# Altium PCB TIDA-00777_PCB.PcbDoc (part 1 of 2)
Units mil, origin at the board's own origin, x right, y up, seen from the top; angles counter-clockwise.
Board outline 1968.5 x 2165.35 mil, 4 copper layers (Top Layer, GND, +2.5V, Bottom Layer), stack 30.48 mil thick; 147 components, 52 nets, 290 pads, 85 vias.
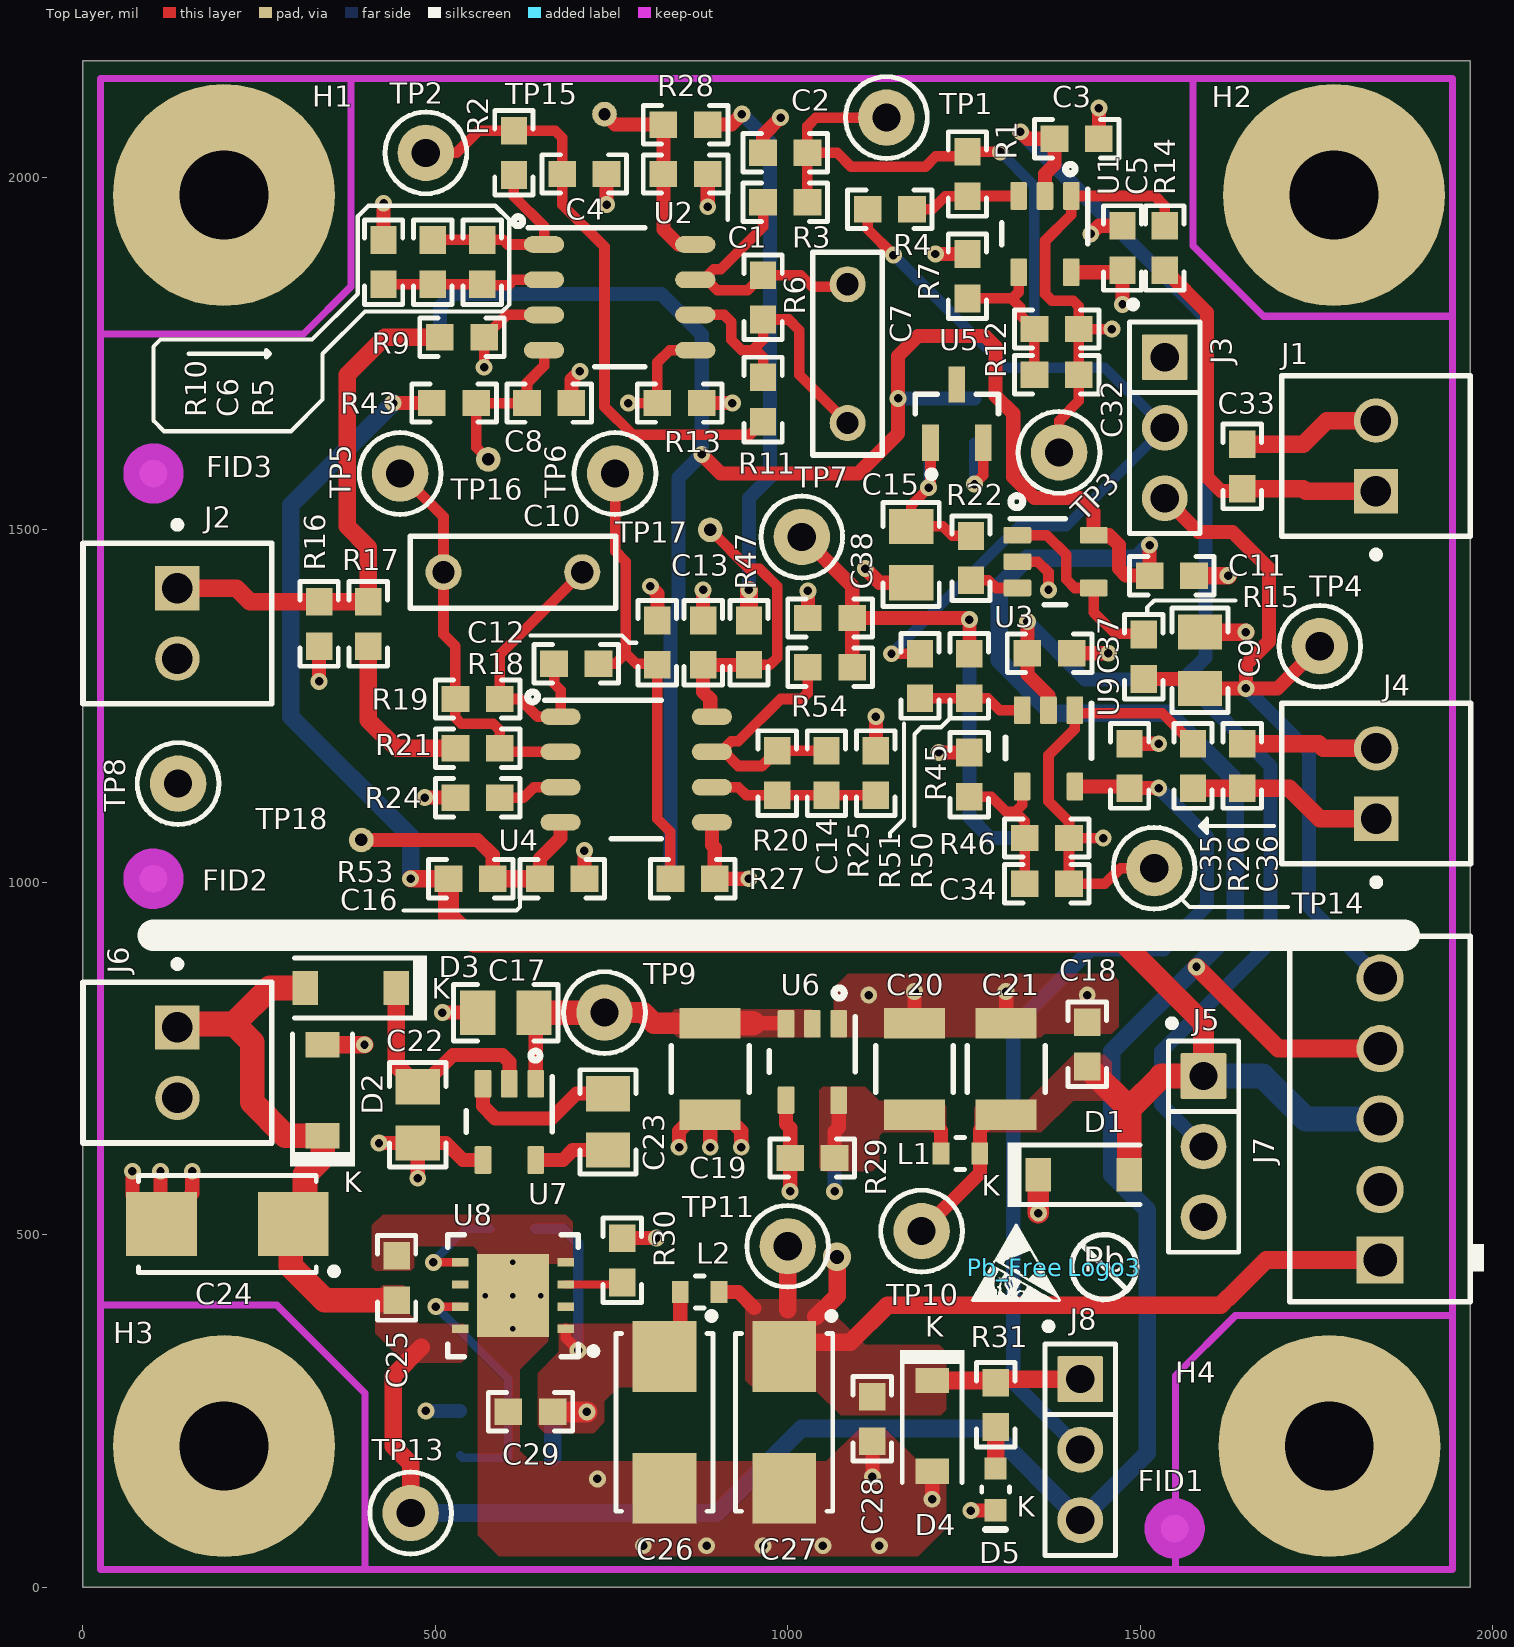
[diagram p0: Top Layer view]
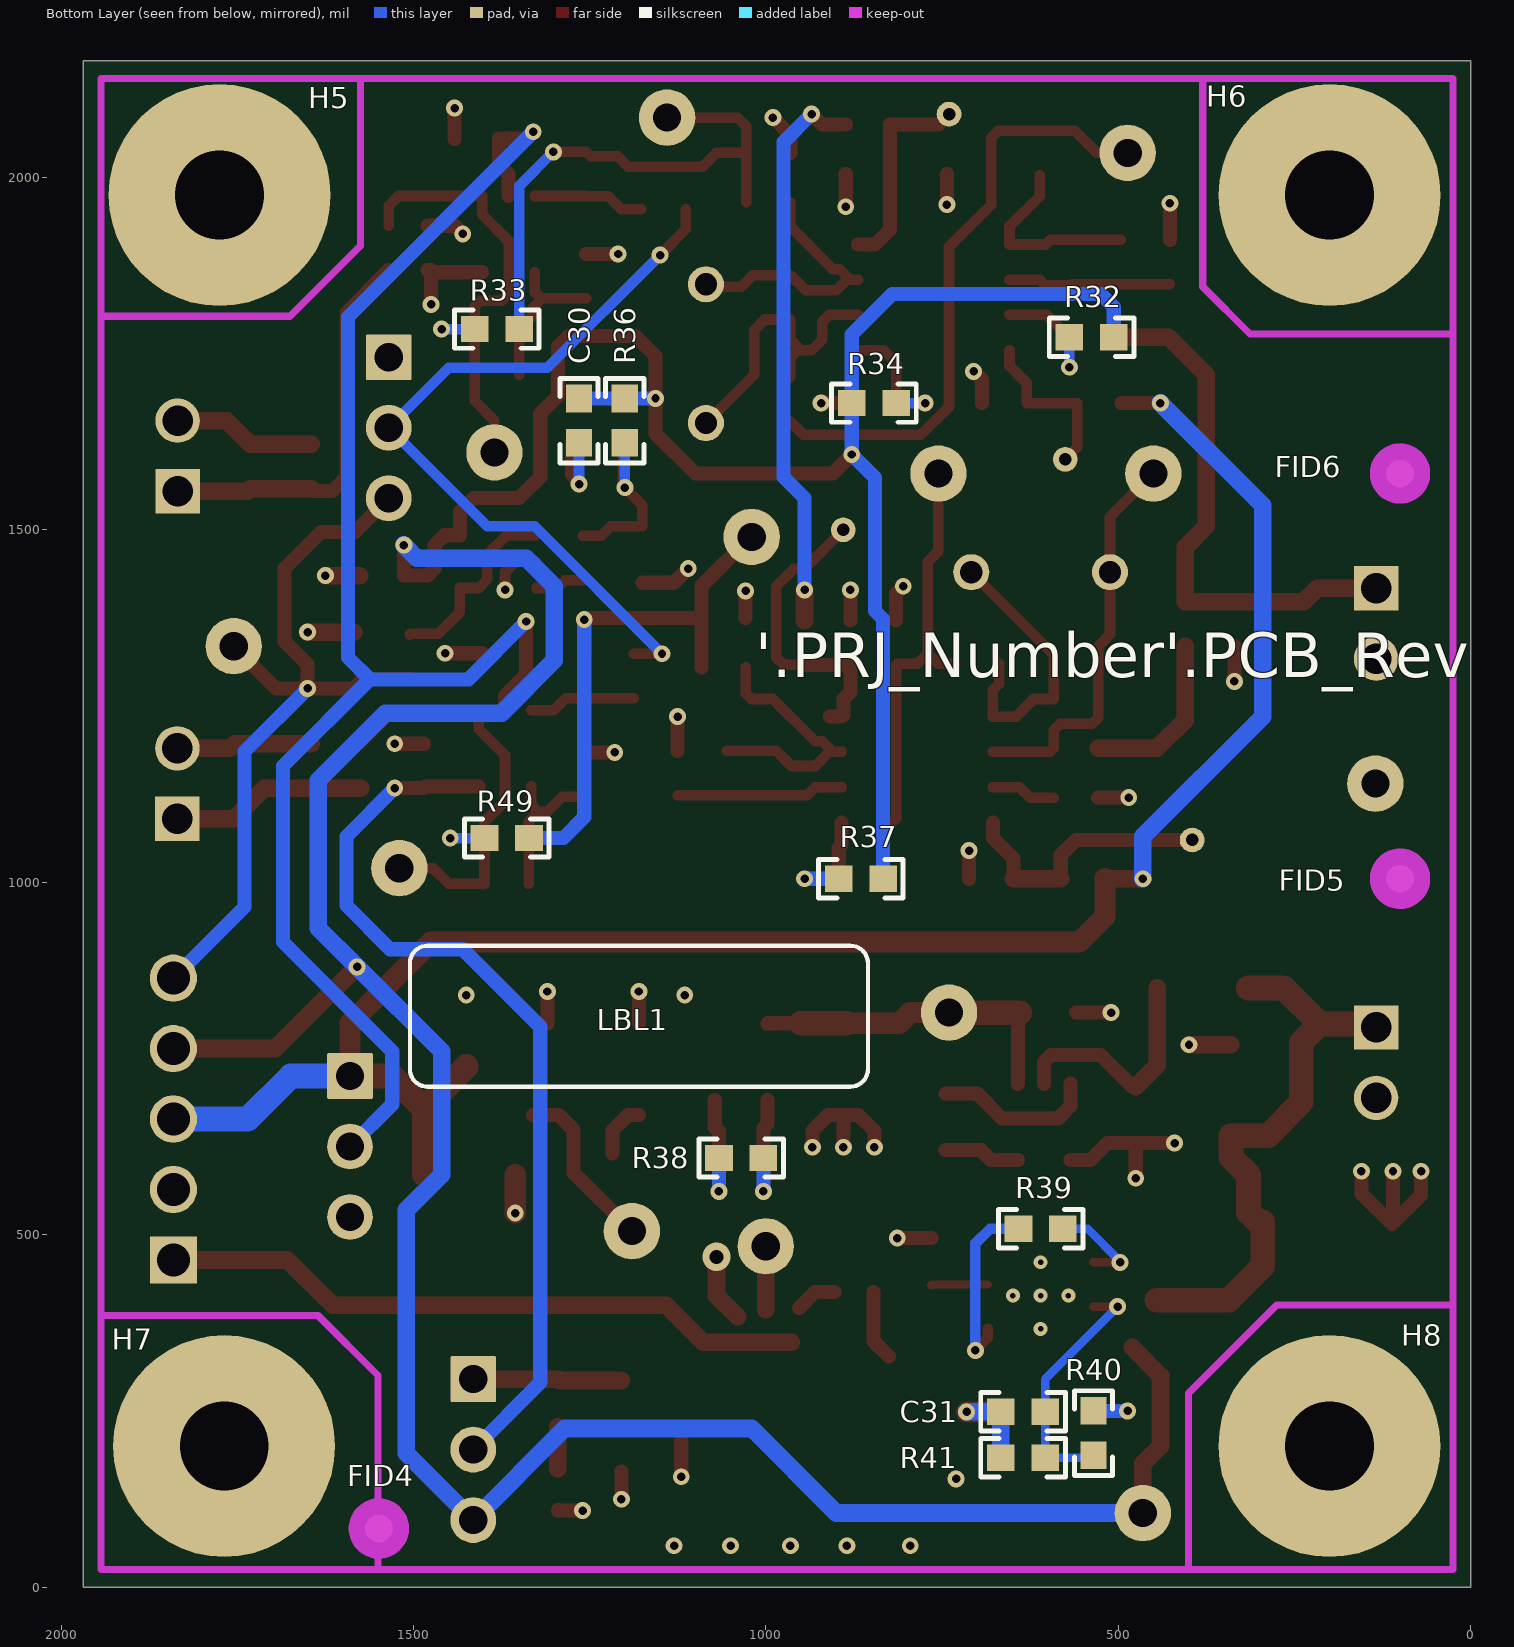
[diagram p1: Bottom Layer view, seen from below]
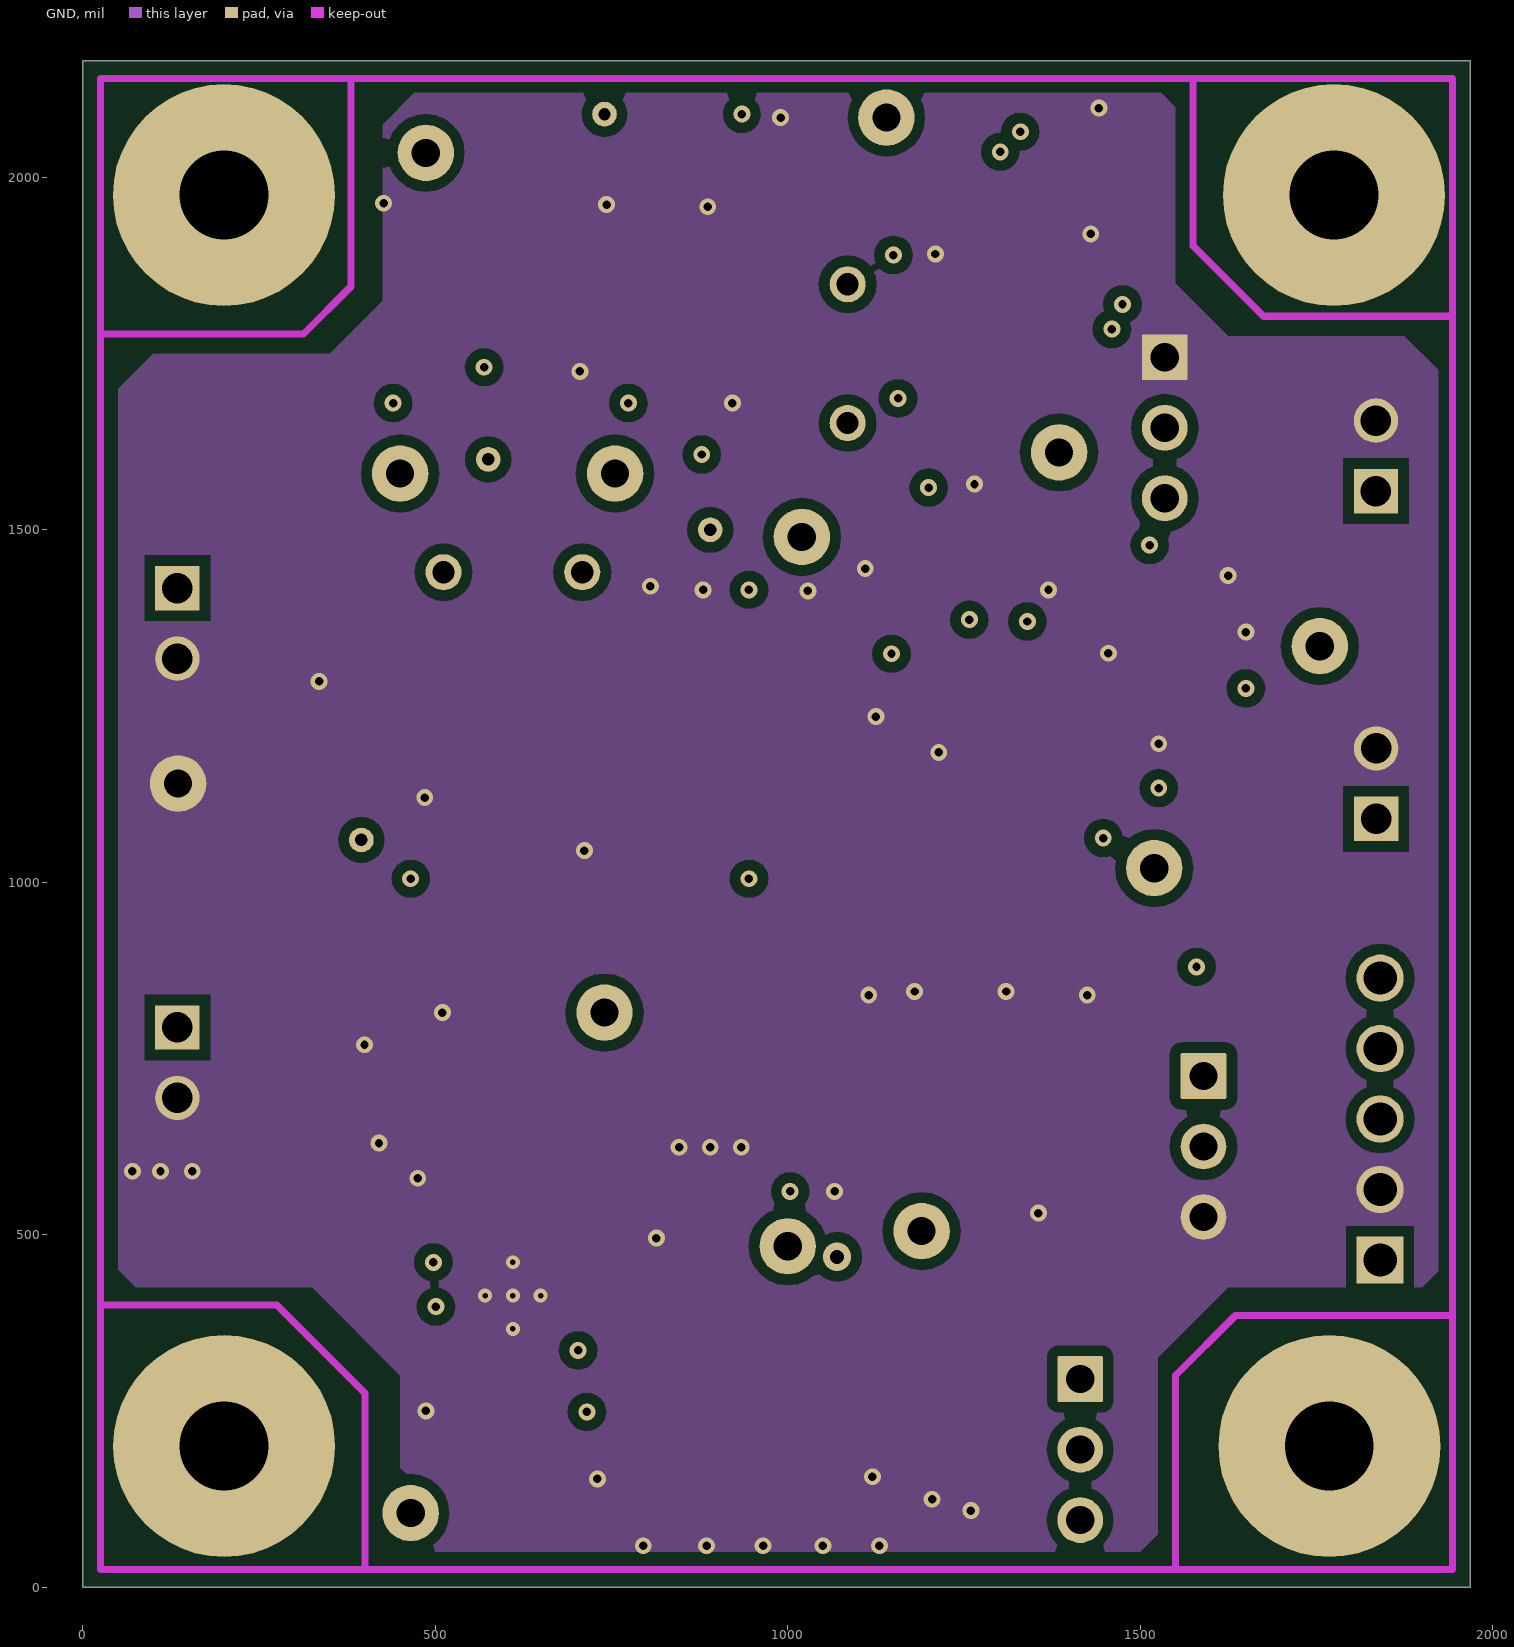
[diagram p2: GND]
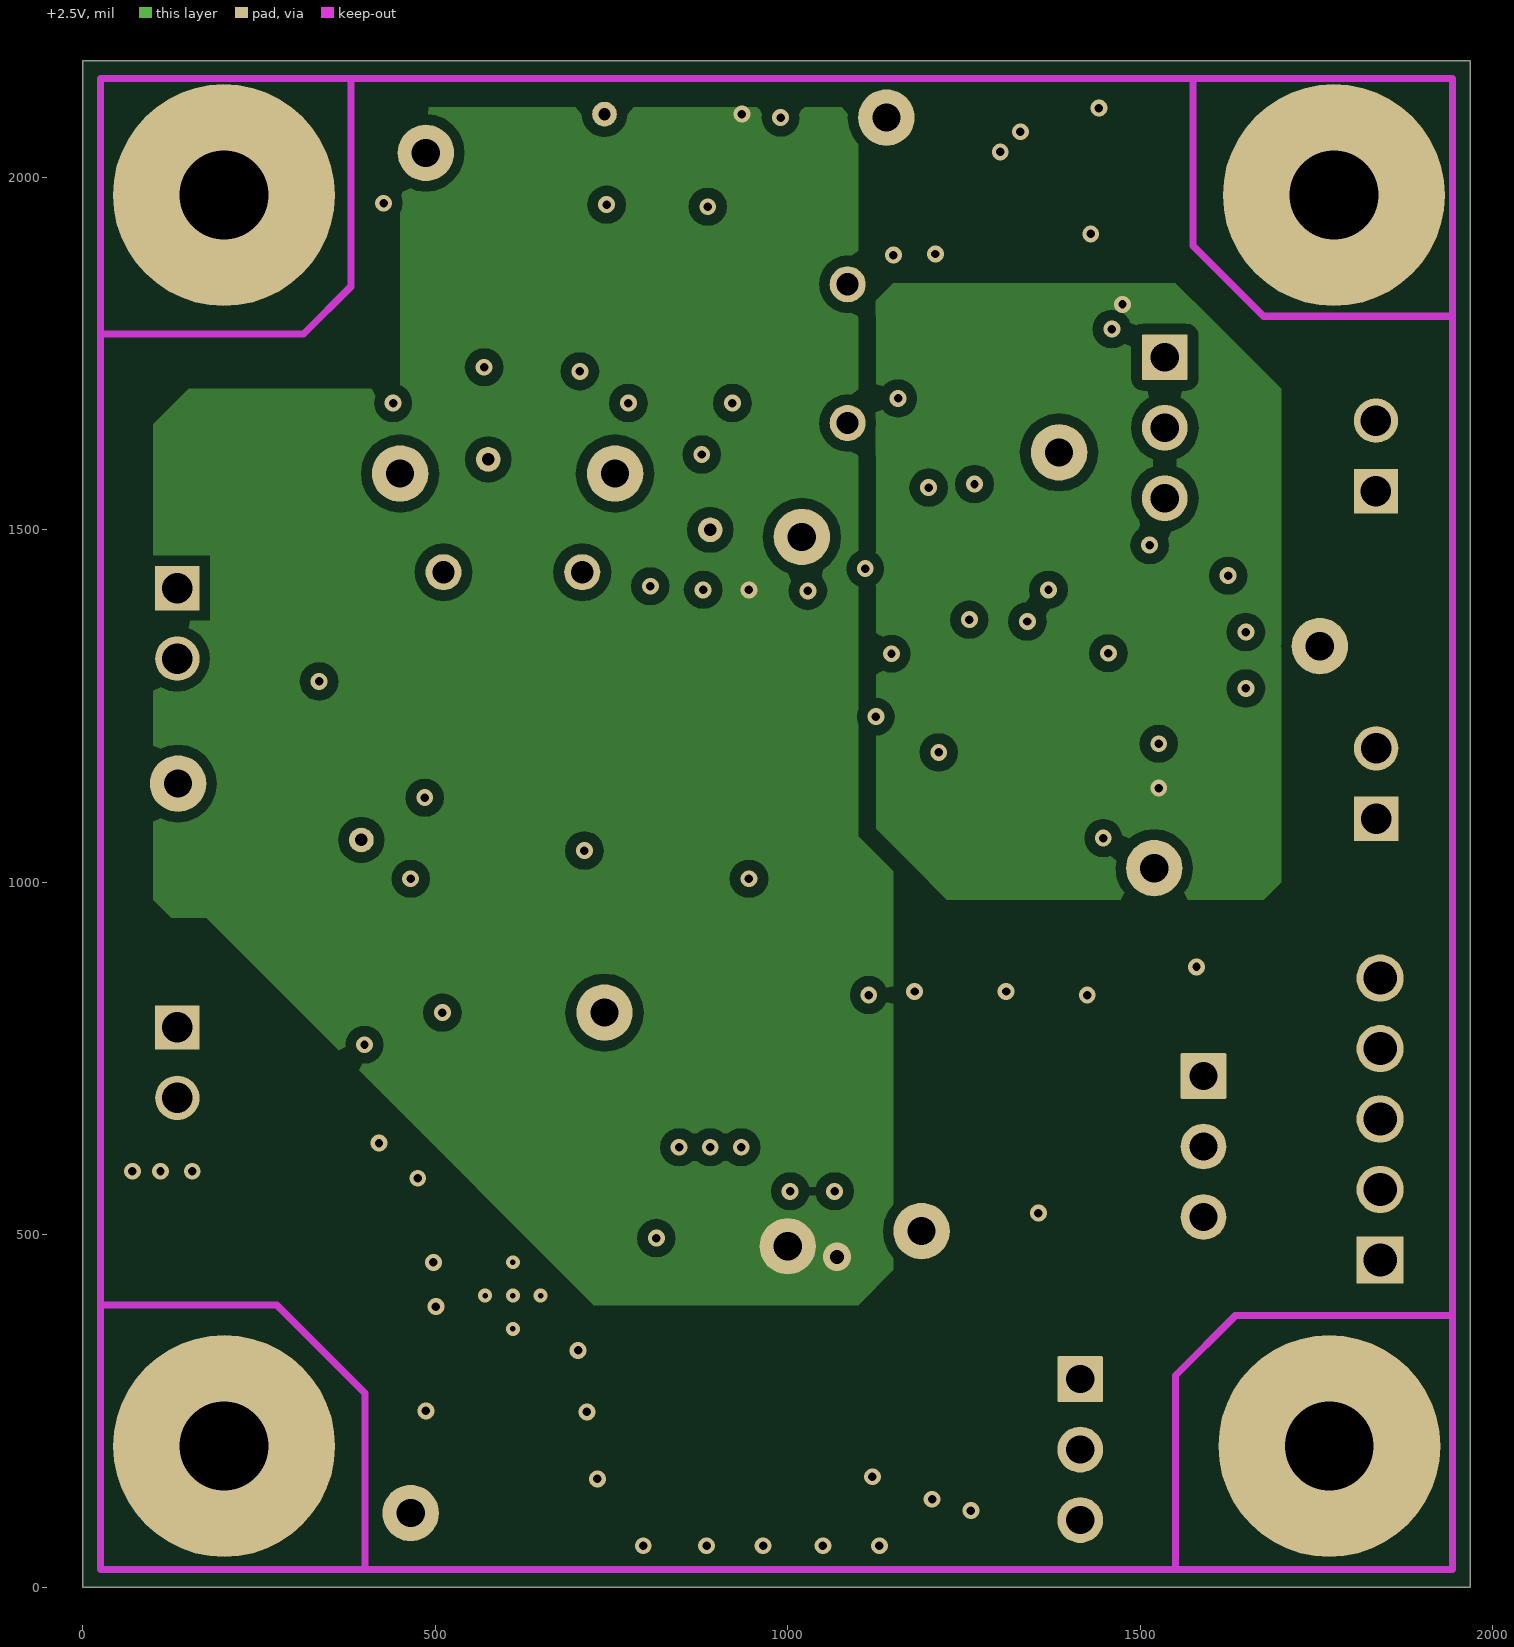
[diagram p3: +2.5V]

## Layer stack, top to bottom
Top Solder: solder mask 0.4, Solder Resist, Dk 3.5
Top Layer: signal copper 1.37
Dielectric1: core 10, FR-4 High Tg, Dk 4.2
GND: signal copper 1.37
Dielectric2: prepreg 5, FR-4 High Tg, Dk 4.2
+2.5V: signal copper 1.37
Dielectric3: core 10, FR-4 High Tg, Dk 4.2
Bottom Layer: signal copper 1.37
Bottom Solder: solder mask 0.4, Solder Resist, Dk 3.5

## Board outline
0,0 0,2165.35 1968.5,2165.35 1968.5,0

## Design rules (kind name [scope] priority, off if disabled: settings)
AcuteAngle [All] p1: minimum=4.50000000000000E+0001 checktracksonly=FALSE
AssemblyTestPointUsage [All] p1: valid=2
BoardOutlineClearance BoardOutlineClearance_MountingHoles [OnCopper and InComponentClass('Mounting Holes')] p1: gap=40
BoardOutlineClearance BoardOutlineClearance_Poly [OnCopper and InPoly] p2: gap=25
BoardOutlineClearance [OnCopper and Not InComponentClass('Logo') and not InComponentClass('FiducialMark') and not InRegion(1000,500,4000,800)] p3: gap=70 except(25: Poly-OutlineEdge; 40: Track-OutlineEdge SMDPad-OutlineEdge THPad-OutlineEdge Via-OutlineEdge)
Clearance Clearance_Keepouts [((IsTrack Or IsArc) And Not InPoly) And IsFree and IsKeepOut vs ((IsTrack Or IsArc) And Not InPoly) And IsFree and IsKeepOut] p1: gap=0
Clearance Clearance_TOP [OnLayer('Top Layer')] p2: gap=7.87 except(7: Track-Poly SMDPad-SMDPad SMDPad-Poly; 25: Arc-Arc)
Clearance Clearance_Poly [InPolygon] p3: gap=25 except(15: Track-Poly THPad-Poly Via-Poly)
Clearance [All] p4: gap=7.87
ComponentClearance ComponentClearance_MountingHoles_FiducialMarks [InComponentClass('Mounting Holes') vs InComponentClass('FiducialMark')] p1: gap=0 collisioncheckmode=3 verticalgap=10 showdistances=FALSE
ComponentClearance ComponentClearance_Shunt [InComponentClass('Header') vs InComponentClass('Shunt')] p2: gap=0 collisioncheckmode=3 verticalgap=0 showdistances=FALSE
ComponentClearance ComponentClearance_Logo [InComponentClass('Logo')] p3: gap=50 collisioncheckmode=3 verticalgap=10 showdistances=FALSE
ComponentClearance ComponentClearance_ScrewToNut [(HasFootprint('NY PMS 440 0025 PH')) vs (HasFootprint('Keystone_1902C'))] p4: gap=5 collisioncheckmode=3 verticalgap=10 showdistances=FALSE
ComponentClearance ComponentClearance_MountingHoles [InComponentClass('Mounting Holes')] p5: gap=75 collisioncheckmode=3 verticalgap=100000 showdistances=FALSE
ComponentClearance ComponentClearance_SmallPassives [HasFootprint('0201*') or HasFootprint('0402*') or HasFootprint('0508') or HasFootprint('0603*') or HasFootprint('0612') or HasFootprint('0805*') or HasFootprint('0815*') or HasFootprint('0830*') or HasFootprint('1206*') or HasFootprint('1210*') or HasFootprint('1808*') or HasFootprint('1812*') or HasFootprint('1825*') or HasFootprint('2010*') or HasFootprint('2220*') or HasFootprint('2225*') or HasFootprint('2512*') or HasFootprint('2728*') or HasFootprint('3518*') vs HasFootprint('0201*') or HasFootprint('0402*') or HasFootprint('0508') or HasFootprint('0603*') or HasFootprint('0612') or HasFootprint('0805*') or HasFootprint('0815*') or HasFootprint('0830*') or HasFootprint('1206*') or HasFootprint('1210*') or HasFootprint('1808*') or HasFootprint('1812*') or HasFootprint('1825*') or HasFootprint('2010*') or HasFootprint('2220*') or HasFootprint('2225*') or HasFootprint('2512*') or HasFootprint('2728*') or HasFootprint('3518*')] p6: gap=14.96 collisioncheckmode=3 verticalgap=10 showdistances=FALSE
ComponentClearance ComponentClearance_THtoSMT [IsThruComponent vs IsSMTComponent] p7: gap=40 collisioncheckmode=3 verticalgap=30 showdistances=FALSE
ComponentClearance ComponentClearance_THtoTH [IsThruComponent vs IsThruComponent] p8: gap=30 collisioncheckmode=3 verticalgap=30 showdistances=FALSE
ComponentClearance [All] p9: gap=30 collisioncheckmode=3 verticalgap=10 showdistances=FALSE
DiffPairsRouting [All] p1: maxlimit=100 minlimit=10 mostfreqgap=10 toplayer_minwidth=15 toplayer_maxwidth=15 toplayer_prefwidth=15 midlayer1_minwidth=15 midlayer1_maxwidth=15 midlayer1_prefwidth=15 midlayer2_minwidth=15 midlayer2_maxwidth=15 midlayer2_prefwidth=15 bottomlayer_minwidth=15 bottomlayer_maxwidth=15 bottomlayer_prefwidth=15 maxuncoupledlength=1000
FabricationTestPointUsage TestPointUsage [All] p1: valid=2 allowmultiple=FALSE
FabricationTestpoint Testpoint [All] p1: side=3 testpointundercomponent=TRUE minsize=40 maxsize=100 preferedsize=60 minholesize=0 maxholesize=40 preferedholesize=32 testpointgrid=1 allowsidetop=TRUE allowsidebottom=TRUE usegrid=TRUE gridtolerance=0.01
FanoutControl Fanout_LCC [IsLCC] p1: bgadir=Out bgaviamode=Centered fanoutstyle=Auto fanoutdirection=Alternating viagrid=1 // Fanout_LCC (Default Rule)
FanoutControl Fanout_BGA [IsBGA] p2: bgadir=Out bgaviamode=Centered fanoutstyle=Auto fanoutdirection=Alternating viagrid=1 // Fanout_BGA (Default Rule)
FanoutControl Fanout_Default [All] p4: bgadir=Out bgaviamode=Centered fanoutstyle=Auto fanoutdirection=Alternating viagrid=1 // Fanout_Default (Default Rule)
FanoutControl Fanout_Small [(CompPinCount < 5)] p5: bgadir=Out bgaviamode=Centered fanoutstyle=Auto fanoutdirection=OutThenIn viagrid=1 // Fanout_Small (Default Rule)
HoleSize [All] p1: absolutevalues=TRUE maxlimit=251 minlimit=7.87 maxpercent=80.000 minpercent=20.000
MinimumAnnularRing MinimumAnnularRing_ThermalPadVias [IsVia and InAnyComponent] p1: minimumring=5.91
MinimumAnnularRing [All] p2: minimumring=6
MinimumSolderMaskSliver MinimumSolderMaskSliver_Logo [InComponentClass('Logo') vs InComponentClass('Logo')] p1: minsoldermaskwidth=0.7
MinimumSolderMaskSliver [All] p2: minsoldermaskwidth=3.94
PlaneConnect [All] p1: planeconnectstyle=Direct reliefexpansion=10 reliefentries=4 reliefconductorwidth=10 reliefairgap=10
PolygonConnect PolygonConnect_Top [All] p1: connectstyle=Direct reliefconductorwidth=10 reliefentries=4 polygonreliefangle="90 Angle" airgapwidth=10
PolygonConnect PolygonConnect_via [All vs IsVia] p2: connectstyle=Direct reliefconductorwidth=10 reliefentries=4 polygonreliefangle="90 Angle" airgapwidth=10
PolygonConnect [All] p3: connectstyle=Relief reliefconductorwidth=15 reliefentries=4 polygonreliefangle="90 Angle" airgapwidth=15
RoutingLayers [All] p1: top layer_v5=TRUE mid layer 1_v5=FALSE mid layer 2_v5=FALSE bottom layer_v5=TRUE
RoutingVias ThermalPadVias [IsVia and InAnyComponent] p1: holewidth=7.87 width=19.68 viastyle="Through Hole" minholewidth=7.87 minwidth=19.68 maxholewidth=12.99 maxwidth=23.62
RoutingVias [All] p2: holewidth=12 width=24 viastyle="Through Hole" minholewidth=10 minwidth=20 maxholewidth=40 maxwidth=65
SilkToBoardRegionClearance [Not ((IsComment or IsDesignator) And (Hide <> 'False')) and not InRegion(1000,500,4000,800)] p1:
SilkToSilkClearance SilkToSilkClearance_Pb-FreeLogo [(HasFootprint('Pb-Free_Overlay_Medium') OR HasFootprint('Pb-Free_Overlay_Small')) vs (HasFootprint('Pb-Free_Overlay_Medium') OR HasFootprint('Pb-Free_Overlay_Small'))] p1: silktosilkclearance=0
SilkToSilkClearance [All] p2: silktosilkclearance=4
SilkToSolderMaskClearance SilkToComponentPadClearance [IsPad and InAnycomponent] p1: minsilkscreentomaskgap=5 clearancetoexposedcopper=TRUE
SilkToSolderMaskClearance "Silk to Solder Mask Opening" [All] p2: minsilkscreentomaskgap=4 clearancetoexposedcopper=FALSE
SolderMaskExpansion [All] p1: expansion=2.5
Width [All] p1: maxlimit=100 minlimit=6 preferedwidth=10 checkconnectedcopper=TRUE
14 further rules are at their usual default settings.

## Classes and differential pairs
component class Label: LBL1
component class AssemblyNote: ZZ1 ZZ2 ZZ3 ZZ4
component class FiducialMark: FID1 FID2 FID3 FID4 FID5 FID6
component class TIDA-00777_EVM_Hardware: FID1 FID2 FID3 FID4 FID5 FID6 H1 H2 H3 H4 H5 H6 H7 H8 LBL1 Logo3 Pb_Free ZZ1 ZZ2 ZZ3 ZZ4
component class "Mounting Holes": H1 H2 H3 H4
component class Header: J3 J7 J8
component class "TIDA-00777_POWER SUPPLY": C17 C18 C19 C20 C21 C22 C23 C24 C25 C26 C27 C28 C29 C31 D1 D2 D3 D4 D5 J5 J6 J7 J8 L1 L2 R29 R30 R31 R38 R39 R40 R41 TP8 TP9 TP10 TP11 TP13 U6 U7 U8
component class "TIDA-00777_SIGNAL CONDITIONING": C1 C2 C3 C4 C5 C6 C7 C8 C9 C10 C11 C12 C13 C14 C15 C16 C30 C32 C33 C34 C35 C36 C37 C38 J1 J2 J3 J4 R1 R2 R3 R4 R5 R6 R7 R9 R10 R11 R12 R13 R14 R15 R16 R17 R18 R19 R20 R21 R22 R24 R25 R26 R27 R28 R32 R33 R34 R36 R37 R43 R45 R46 R47 R49 R50 R51 R53 R54 TP1 TP2 TP3 TP4 TP5 TP6 TP7 TP14 TP15 TP16 TP17 TP18 U1 U2 U3 U4 U5 U9

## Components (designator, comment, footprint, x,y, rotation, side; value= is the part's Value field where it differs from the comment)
C1 "06033C104JAT2A" 0603 855,2005 r180 top (schematic designator C4)
C2 "06035A101FAT2A" 0603 996.5,2035 r180 top (schematic designator C8)
C3 "06033C104JAT2A" 0603 1410,2055 r180 top (schematic designator C6)
C4 "06035A101FAT2A" 0603 711.5,2005 r0 top (schematic designator C23)
C5 "06033C104JAT2A" 0603 1475,1900 r270 top (schematic designator C3)
C6 "06035A101FAT2A" 0603 496.5,1880 r90 top (schematic designator C2)
C7 "B32529C154J289" B32529_730x250x650 1085,1750 r270 top (schematic designator C1)
C8 "06033C104JAT2A" 0603 661.5,1680 r180 top (schematic designator C7)
C9 "GRM21BR71H105KA12L" 0805_HV 1585,1315 r90 top (schematic designator C14)
C10 "R82DC3100DQ50J" R82_720x250x650 610,1440 r180 top
C11 "06033C104JAT2A" 0603 1545,1435 r180 top (schematic designator C13)
C12 "06035A101FAT2A" 0603 815,1340 r90 top
C13 "06033C104JAT2A" 0603 880,1340 r270 top (schematic designator C5)
C14 "06035A101FAT2A" 0603 1055,1155 r90 top (schematic designator C11)
C15 "GRM21BR71H105KA12L" 0805_HV 1175,1465 r270 top (schematic designator C16)
C16 "06033C104JAT2A" 0603 680,1005 r180 top (schematic designator C9)
C17 "GRM21BR71H105KA12L" 0805_HV 600,815 r180 top (schematic designator C26)
C18 "06033C104JAT2A" 0603 1425,770 r90 top (schematic designator C33)
C19 "12103C106KAT2A" 1210_280 890,735 r270 top (schematic designator C29)
C20 "12103C106KAT2A" 1210_280 1180,735 r90 top (schematic designator C34)
C21 "12103C106KAT2A" 1210_280 1310,735 r90 top (schematic designator C32)
C22 "GRM21BR71H105KA12L" 0805_HV 475,670 r270 top (schematic designator C25)
C23 "GRM21BR71H105KA12L" 0805_HV 745,660 r270 top (schematic designator C28)
C24 "293D106X9025C2TE3" 6032-28 205,515 r180 top (schematic designator C18)
C25 "06033C104JAT2A" 0603 445,438.5 r90 top (schematic designator C21)
C26 "293D106X9025C2TE3" 6032-28 825,233.5 r270 top (schematic designator C19)
C27 "293D106X9025C2TE3" 6032-28 995,233.5 r270 top (schematic designator C20)
C28 "06033C104JAT2A" 0603 1120,238.5 r270 top (schematic designator C17)
C29 "06033C104JAT2A" 0603 635,248.5 r180 top (schematic designator C22)
C30 "06033C104JAT2A" 0603 1265,1655 r90 bottom (schematic designator C15)
C31 "06035A101FAT2A" 0603 635,248.5 r180 bottom (schematic designator C24)
C32 "06035A101FAT2A" 0603 1381.5,1720 r0 top
C33 "06035A101FAT2A" 0603 1645,1590 r270 top
C34 "06035A101FAT2A" 0603 1367.64,997.76 r0 top
C35 "06033C104JAT2A" 0603 1485,1165 r270 top
C36 "06035A101FAT2A" 0603 1645,1165 r270 top
C37 "06033C104JAT2A" 0603 1371.5,1325 r180 top
C38 "06035A101FAT2A" 0603 1060,1375 r180 top
D1 "MMSZ5223B-7-F" SOD-123 1420,585 r0 top (schematic designator D4)
D2 "MMSZ5232B-7-F" SOD-123 340,705 r90 top
D3 "MBR0520LT1G" SOD-123 380,850 r180 top
D4 "MMSZ5223B-7-F" SOD-123 1205,228.5 r270 top (schematic designator D2)
D5 "LG L29K-G2J1-24-Z" "LG L29K_GREEN" 1295,138.5 r270 top
FID1 "Fiducial" Fiducial10-20 1549,83 r0 top (schematic designator FID3)
FID2 "Fiducial" Fiducial10-20 100,1005 r0 top (schematic designator FID1)
FID3 "Fiducial" Fiducial10-20 100,1580 r0 top (schematic designator FID2)
FID4 "Fiducial" Fiducial10-20 1549,83 r180 bottom
FID5 "Fiducial" Fiducial10-20 100,1005 r180 bottom (schematic designator FID6)
FID6 "Fiducial" Fiducial10-20 100,1580 r180 bottom (schematic designator FID5)
H1 "NY PMS 440 0025 PH" "NY PMS 440 0025 PH"#1 200,1975 r0 top
H2 "NY PMS 440 0025 PH" "NY PMS 440 0025 PH"#1 1775,1975 r0 top (schematic designator H4)
H3 "NY PMS 440 0025 PH" "NY PMS 440 0025 PH"#2 200,200 r0 top (schematic designator H2)
H4 "NY PMS 440 0025 PH" "NY PMS 440 0025 PH"#1 1768.5,200 r0 top (schematic designator H3)
H5 "1902C" Keystone_1902C 1775,1975 r180 bottom (schematic designator H6)
H6 "1902C" Keystone_1902C 200,1975 r180 bottom (schematic designator H8)
H7 "1902C" Keystone_1902C 1768.5,200 r180 bottom (schematic designator H5)
H8 "1902C" Keystone_1902C 200,200 r180 bottom (schematic designator H7)
J1 "282834-2" TEC_282834-2 1834.65,1605 r90 top
J2 "282834-2" TEC_282834-2 133.86,1367.24 r270 top
J3 "HTSW-103-07-G-S" Samtec_HTSW-103-07-G-S 1535,1645 r270 top (schematic designator J5)
J4 "282834-2" TEC_282834-2 1835,1140 r90 top (schematic designator J3)
J5 "282834-5" TE_282834-5 1840.55,664.06 r90 top (schematic designator J7)
J6 "282834-2" TEC_282834-2 133.86,743.98 r270 top
J7 "HTSW-103-07-G-S" Samtec_HTSW-103-07-G-S 1590,625 r270 top (schematic designator J13)
J8 "HTSW-103-07-G-S" Samtec_HTSW-103-07-G-S 1415,195 r270 top (schematic designator J12)
L1 "MMZ1608B102CTA00" MMZ1608_095 1245,615 r0 top (schematic designator L3)
L2 "MMZ1608B102CTA00" MMZ1608_095 875,418.5 r0 top (schematic designator L1)
LBL1 "Size: 0.65\" x 0.20 \"" Label_650x200 1180,810 r180 bottom
Logo3 "Pb-Free Symbol" Pb-Free_Overlay_Small 1449,454 r0 top
Pb_Free "ESD Susceptible" ESD_Overlay_small 1323,454 r0 top
R1 "RG1608P-104-B-T5" 0603 1255,2005 r270 top (schematic designator R8)
R2 "RC0603JR-070RL" 0603 611.5,2035 r90 top (schematic designator R15)
R3 "RC0603JR-070RL" 0603 996.5,1965 r0 top (schematic designator R9)
R4 "RG1608P-104-B-T5" 0603 1145,1955 r0 top (schematic designator R11)
R5 "RG1608P-154-B-T5" 0603 566.5,1880 r90 top (schematic designator R2)
R6 "CPF0603B680KE1" 0603 965,1830 r90 top (schematic designator R5)
R7 "RG1608P-104-B-T5" 0603 1255,1860 r270 top (schematic designator R3)
R9 "RG1608P-1052-B-T5" 0603 537.8,1773.23 r0 top (schematic designator R10)
R10 "RG1608P-1132-B-T5" 0603 426.5,1880 r270 top (schematic designator R1)
R11 "RP73PF1J20K5BTDF" 0603 965,1685 r90 top (schematic designator R7)
R12 "RG1608P-104-B-T5" 0603 1381.5,1785 r0 top (schematic designator R4)
R13 "RC0603JR-070RL" 0603 846.5,1680 r180 top (schematic designator R36)
R14 "RG1608P-101-B-T5" 0603 1535,1900 r270 top (schematic designator R28)
R15 "CRCW0603100RFKEA" 0603 1505,1320 r270 top (schematic designator R33)
R16 "CRCW0603100KFKEA" 0603 335,1366.5 r90 top (schematic designator R12)
R17 "RC0603JR-070RL" 0603 405,1366.5 r90 top (schematic designator R32)
R18 "RC0603JR-070RL" 0603 700,1310 r0 top (schematic designator R21)
R19 "ERA-3AEB1373V" 0603 560,1260 r0 top (schematic designator R17)
R20 "CRCW0603150KFKEA" 0603 985,1155 r90 top (schematic designator R14)
R21 "RC0603FR-0730K9L" 0603 560,1190 r0 top (schematic designator R19)
R22 "CRCW0603100RFKEA" 0603 1260,1460 r270 top (schematic designator R25)
R24 "RC0603JR-070RL" 0603 560,1120 r0 top (schematic designator R37)
R25 "CRCW060311K0FKEA" 0603 1125,1155 r270 top (schematic designator R13)
R26 "CRCW0603100RFKEA" 0603 1575,1165 r270 top (schematic designator R34)
R27 "RG1608P-1022-B-T5" 0603 865,1005 r0 top (schematic designator R22)
R28 "RC0603JR-070RL" 0603 855,2075 r180 top (schematic designator R23)
R29 "CRCW060318K0FKEA" 0603 1035,608.7 r0 top
R30 "RC0603JR-070RL" 0603 765,463.5 r270 top (schematic designator R39)
R31 "RC0603FR-07510RL" 0603 1295,258.5 r90 top (schematic designator R35)
R32 "CRCW0603300KFKEA" 0603 537.8,1773.23 r0 bottom (schematic designator R20)
R33 "RC0603JR-070RL" 0603 1381.5,1785 r0 bottom (schematic designator R24)
R34 "CRCW0603100KFKEA" 0603 846.5,1680 r0 bottom (schematic designator R16)
R36 "CRCW06032K55FKEA" 0603 1200,1655 r270 bottom (schematic designator R31)
R37 "CRCW0603300KFKEA" 0603 865,1005 r0 bottom (schematic designator R38)
R38 "RC0603FR-0710KL" 0603 1035,608.7 r180 bottom (schematic designator R30)
R39 "CRCW0603100KFKEA" 0603 610,508.5 r0 bottom (schematic designator R26)
R40 "RC0603FR-0720KL" 0603 535,218.5 r270 bottom (schematic designator R42)
R41 "RC0603FR-0720K5L" 0603 635,183.5 r0 bottom (schematic designator R40)
R43 "RC0603JR-070RL" 0603 526.5,1680 r0 top
R45 "CRCW0603100KFKEA" 0603 1257.64,1152.76 r270 top
R46 "CRCW0603100KFKEA" 0603 1367.64,1062.76 r0 top
R47 "RC0603JR-070RL" 0603 945,1340 r270 top
R49 "RC0603JR-070RL" 0603 1367.64,1062.82 r0 bottom
R50 "CRCW0603100KFKEA" 0603 1257.64,1292.76 r270 top
R51 "CRCW0603100KFKEA" 0603 1187.64,1292.76 r270 top
R53 "RC0603JR-070RL" 0603 550,1005 r0 top
R54 "RC0603JR-070RL" 0603 1060,1305 r0 top
TP1 "5000" Keystone5000 1140,2085 r90 top (schematic designator TP3)
TP2 "5000" Keystone5000 486.5,2035 r90 top
TP3 "5000" Keystone5000 1385,1610 r270 top (schematic designator TP1)
TP4 "5000" Keystone5000 1755,1335 r180 top (schematic designator TP13)
TP5 "5000" Keystone5000 450,1580 r180 top (schematic designator TP16)
TP6 "5000" Keystone5000 755,1580 r180 top
TP7 "5000" Keystone5000 1020,1490 r180 top (schematic designator TP5)
TP8 "5000" Keystone5000 135,1140 r180 top (schematic designator TP14)
TP9 "5000" Keystone5000 740,815 r0 top (schematic designator TP10)
TP10 "5000" Keystone5000 1190,505 r180 top (schematic designator TP11)
TP11 "5000" Keystone5000 1000,483.5 r180 top (schematic designator TP9)
TP13 "5000" Keystone5000 465,105 r180 top (schematic designator TP7)
TP14 "5000" Keystone5000 1520,1020 r0 top
TP15 "TESTPOINT" TP_H045P075 740,2090 r270 top
TP16 "TESTPOINT" TP_H045P075 575,1600 r270 top
TP17 "TESTPOINT" TP_H045P075 890,1500 r270 top
TP18 "TESTPOINT" TP_H045P075 395,1060 r270 top
U1 "OPA188AIDBVR" DBV0005A_N 1365,1919.68 r270 top
U2 "OPA2188AID" D0008A_N 761.5,1830 r0 top (schematic designator U3)
U3 "OPA188AIDBVR" DBV0005A_N 1380,1455 r0 top (schematic designator U5)
U4 "OPA2188AID" D0008A_N 785,1160 r0 top (schematic designator U2)
U5 "LM4040AIM3-2.5/NOPB" MF03A_N 1240,1665 r90 top (schematic designator U4)
U6 "TPS72325DBVT" DBV0005A_N 1035,745 r270 top (schematic designator U8)
U7 "TPS60403DBVR" DBV0005A_N 605,660 r270 top
U8 "LP2951ACSD/NOPB" SDC08A 610,413.5 r180 top (schematic designator U6)
U9 "OPA188AIDBVR" DBV0005A_N 1370,1190 r270 top
ZZ1 "This Assembly Note is for PCB labels only" AssemblyNoteLabel 60,2768 r0 top (schematic designator ZZ4)
ZZ2 "These assemblies are ESD sensitive, ESD precautions shall be observed." AssemblyNote 60,2659.11 r0 top (schematic designator ZZ3)
ZZ3 "These assemblies must be clean and free from flux and all contaminants. Use of no clean flux is not acceptable." AssemblyNote 60,2570.56 r0 top (schematic designator ZZ2)
ZZ4 "These assemblies must comply with workmanship standards IPC-A-610 Class 2, unless otherwise specified." AssemblyNote 60,2482 r0 top (schematic designator ZZ1)

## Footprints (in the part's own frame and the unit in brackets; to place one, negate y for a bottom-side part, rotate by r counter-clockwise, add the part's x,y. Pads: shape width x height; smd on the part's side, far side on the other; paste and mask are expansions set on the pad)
0603 [mm] "0603 from SM-752 data"
  rect 1x0.95 smd: 1(-0.8,0) 2(0.8,0)
  silkscreen extent -1.52,-0.69 1.52,0.69, body extent -0.87,-0.47 0.87,0.47, height 1
0805_HV [mil] "0805 with 30mil clearance between pads"
  rect 50x63 smd: 1(-40,0) 2(40,0)
  silkscreen extent -74,-40 74,40, body extent -43,-29 43,29, height 57
1210_280 [mm] "SMD, 2-Leads, Body 3.6x2.8mm, Height 2.8mm"
  rect 1.1x2.2 smd: 1(-1.65,0) 2(1.65,0)
  silkscreen extent -0.84,-1.4 0.84,1.4, body extent -1.8,-1.4 1.8,1.4, height 2.8
6032-28 [mm] "Medium Density IPC based on Vishay Sprague 293D datasheet."
  rect 2.55x2.3 smd: 1(-2.375,0) 2(2.375,0)
  silkscreen extent -3.96,-1.75 3.2,1.82, body extent -3.15,-1.75 3.15,1.75, height 2.8
AssemblyNote [mil] "Assembly Note"
AssemblyNoteLabel [mil] "Assembly Note for PCB Labels"
B32529_730x250x650 [mm] "TH, 2-Leads, Body 7.3x2.5mm"
  round 1.3 hole 0.8: 1(-2.5,0) 2(2.5,0)
  silkscreen extent -3.65,-1.25 3.65,1.25, body extent -3.65,-1.25 3.65,1.25, height 6.5
D0008A_N [mm] "SOIC, 8-Leads, Body 4.9x3.9mm, Pitch 1.27mm, IPC Medium Density"
  oval 1.45x0.6 smd: 1(-2.725,1.905) 2(-2.725,0.635) 3(-2.725,-0.635) 4(-2.725,-1.905) 5(2.725,-1.905) 6(2.725,-0.635) 7(2.725,0.635) 8(2.725,1.905)
  silkscreen extent -3.3,-2.5 0.9,2.5, body extent -3,-2.45 3,2.45, height 1.63
DBV0005A_N [mm] "SOT23, 5-Leads, Body 2.9x1.6mm, Pitch 0.95mm, Lead Span 2.8mm, IPC Medium Density"
  rrect17% 1x0.6 smd: 1(-1.375,0.95) 2(-1.375,0) 3(-1.375,-0.95) 4(1.375,-0.95) 5(1.375,0.95)
  silkscreen extent -1.63,-1.55 0.38,1.55, body extent -1.42,-1.46 1.42,1.46, height 1.09
ESD_Overlay_small [mil]
  silkscreen extent -62,-48 64,61
Fiducial10-20 [mm]
  round 1 smd mask+0.5: 1(0,0)
  Top Layer keep-out circle w1.178: c0,0 r0.5
Keystone5000 [mil] "For Keystone 500x miniature loop terminals"
  round 80 hole 40: 1(0,0)
  silkscreen extent -58,-58 58,58, body extent -49,-49 49,49, height 182
Keystone_1902C [mil] "Hex Standoff, 4-40 threaded, nylon"
  round 1 on Mech4: 0(0,0)
  body extent -145,-126 146,126, height 501
Label_650x200 [mil] "Thermal Transfer Label"
  silkscreen extent -325,-100 325,100, body extent -325,-100 325,100, height 1
"LG L29K_GREEN" [mm] "OSRAM"
  rect 0.8x0.8 smd: 1(-0.75,0) 2(0.75,0)
  silkscreen extent -0.1,-0.5 1.45,0.5, body extent -0.9,-0.45 0.9,0.45, height 0.67
MF03A_N [mm] "SOT23, 3-Leads, Body 2.9x1.3mm, Pitch 0.95mm, Lead Span 2.4mm, IPC Medium Density"
  rect 1.3x0.6 smd: 1(-1.05,0.95) 2(-1.05,-0.95) 3(1.05,0)
  silkscreen extent -2.31,-1.5 0.7,1.5, body extent -0.7,-1.5 0.7,1.5, height 1.12
MMZ1608_095 [mm] "TDK"
  rect 0.6x0.8 smd: 1(-0.7,0) 2(0.7,0)
  silkscreen extent -0.15,-0.58 0.15,0.58, body extent -0.87,-0.47 0.87,0.47, height 0.95
"NY PMS 440 0025 PH"#1 [mm] "4-40 nylon screw and mounting hole"
  round 8 hole 3.2: 1(0,0)
  body extent -3.3,-3.3 3.3,3.3, height 2.69
"NY PMS 440 0025 PH"#2 [mm] "4-40 nylon screw and mounting hole"
  round 8 hole 3.2: 1(0.008,0)
  body extent -3.3,-3.3 3.3,3.3, height 2.69
Pb-Free_Overlay_Small [mil]
  silkscreen extent -46,-46 46,46
R82_720x250x650 [mm] "TH, 2-Leads, Body 7.2x2.5mm, Lead Spacing 5mm"
  round 1.3 hole 0.8: 1(-2.5,0) 2(2.5,0)
  silkscreen extent -3.7,-1.3 3.7,1.3, body extent -3.7,-1.3 3.7,1.3, height 6.6
Samtec_HTSW-103-07-G-S [mm] "Samtec 100mil, 1x3, 230 mil above insulator"
  rrect6% 1.65x1.65 hole 1.016: 1(-2.54,0)
  round 1.65 hole 1.016: 2(0,0) 3(2.54,0)
  silkscreen extent -4.57,-1.27 3.81,1.27, body extent -3.81,-1.27 3.81,1.27, height 8.38
SDC08A [mm] "SON, 8-Leads, Body 4x4mm, Pitch 0.8mm, NSC Recommended"
  rect 0.6x0.3 smd: 1(-1.9,1.2) 2(-1.9,0.4) 3(-1.9,-0.4) 4(-1.9,-1.2) 5(1.9,-1.2) 7(1.9,0.4) 8(1.9,1.2)
  rect 0.6x0.3 smd paste+0: 6(1.9,-0.4)
  rect 2.6x3 smd paste-1.5: 9(0,0)
  silkscreen extent -3.03,-2.2 2.35,2.2, body extent -2.05,-2.05 2.05,2.05, height 0.8
SOD-123 [mm] "On Semi recommended land pattern"
  rect 0.915x1.22 smd: 1(-1.637,0) 2(1.637,0)
  silkscreen extent -2.74,-1.17 2.03,1.17, body extent -1.93,-0.9 1.93,0.9, height 1.35
TE_282834-5 [mm] "Terminal Block, 2.54mm, 5 Pos, R/A, TH"
  rect 1.7x1.7 hole 1.2: 1(-5.08,0)
  round 1.7 hole 1.2: 2(-2.54,0) 3(0,0) 4(2.54,0) 5(5.08,0)
  silkscreen extent -6.58,-3.75 6.58,3.25, body extent -6.58,-3.25 6.58,3.25, height 10.01
TEC_282834-2 [mm] "TEC"
  rect 1.6x1.6 hole 1.1: 1(-1.27,0)
  round 1.6 hole 1.1: 2(1.27,0)
  silkscreen extent -3.66,-3.4 2.9,3.4, body extent -2.77,-3.25 2.77,3.25, height 10.01
TP_H045P075 [mil] "TP_H0.45P0.75"
  round 35 hole 17.72: 1(0,0)

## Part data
C1 C3 C5 C8 C11 C13 C16 C18 C25 C28 C29 C30 C35 C37: "CAP, CERM, 0.1 µF, 25 V, +/- 5%, X7R, 0603"
C2 C4 C6 C12 C14 C31 C32 C33 C34 C36 C38: "CAP, CERM, 100 pF, 50 V, +/- 1%, C0G/NP0, 0603"
C7: "CAP, FILM, 0.15uF, 63VDC, 5%, RADIAL-2P"
C9 C15 C17 C22 C23: "CAP, CERM, 1 µF, 50 V, +/- 10%, X7R, 0805"
C10: "CAP, Film, 0.1 µF, 63 V, +/- 5%, TH"
C19 C20 C21: "CAP, CERM, 10 µF, 25 V, +/- 10%, X7R, 1210"
C24 C26 C27: "CAP, TA, 10 µF, 25 V, +/- 10%, 1.5 ohm, SMD"
D1 D4: "Diode, Zener, 2.7 V, 500 mW, SOD-123"
D2: "Diode, Zener, 5.6 V, 500 mW, SOD-123"
D3: "Diode, Schottky, 20 V, 0.5 A, SOD-123"
D5: "LED, Green, SMD"
FID1 FID2 FID3 FID4 FID5 FID6: "Fiducial mark.  There is nothing to buy or mount."
H1 H2 H3 H4: "Machine Screw, Round, #4-40 x 1/4, Nylon, Philips panhead"
H5 H6 H7 H8: "Standoff, Hex, 0.5\"L #4-40 Nylon"
J1 J2 J4 J6: "Terminal Block, 2x1, 2.54mm, TH"
J3 J7 J8: "Header, 100mil, 3x1, Gold, TH"
J5: "Terminal Block, 2.54mm, 5 Pos, Tin, Green, R/A, TH"
L1 L2: "Ferrite Bead, 1000 ohm @ 100 MHz, 0.3 A, 0603"
LBL1: library part THT-14-423-10, "Thermal Transfer Printable Labels, 0.650\" W x 0.200\" H - 10,000 per roll"
Logo3: library part Pb-Free
Pb_Free: library part ESD_Susceptible, "ESD Susceptible Symbol"
R1 R4 R7 R12: "RES, 100 k, 0.1%, 0.1 W, 0603"
R2 R3 R13 R17 R18 R24 R28 R30 R33 R43 R47 R49 R53 R54: "RES, 0, 5%, 0.1 W, 0603"
R5: "RES, 150 k, 0.1%, 0.1 W, 0603"
R6: library part RC0603FR-07680KL, "RES SMD 680K OHM 0.1% 1/16W 0603"
R9: "RES, 10.5 k, 0.1%, 0.1 W, 0603"
R10: "RES, 11.3 k, 0.1%, 0.1 W, 0603"
R11: library part CRCW060320K5FKEA, "RES SMD 20.5K OHM 0.1% 1/6W 0603"
R14: "RES, 100, 0.1%, 0.1 W, 0603"
R15 R22 R26: "RES, 100, 1%, 0.1 W, 0603"
R16 R34 R39 R45 R46 R50 R51: "RES, 100 k, 1%, 0.1 W, 0603"
R19: library part RT0603BRD07137KL, "RES SMD 137K OHM 0.1% 1/10W 0603"
R20: "RES, 150 k, 1%, 0.1 W, 0603"
R21: "RES, 30.9 k, 1%, 0.1 W, 0603"
R25: "RES, 11.0 k, 1%, 0.1 W, 0603"
R27: "RES, 10.2 k, 0.1%, 0.1 W, 0603"
R29: library part RC0603FR-0718KL, "RES, 18.0 k, 1%, 0.1 W, 0603"
R31: "RES, 510, 1%, 0.1 W, 0603"
R32 R37: "RES, 300 k, 1%, 0.1 W, 0603"
R36: "RES, 2.55 k, 1%, 0.1 W, 0603"
R38: "RES, 10.0 k, 1%, 0.1 W, 0603"
R40: "RES, 20.0 k, 1%, 0.1 W, 0603"
R41: "RES, 20.5 k, 1%, 0.1 W, 0603"
TP1 TP2 TP3 TP4 TP5 TP6 TP7 TP8 TP9 TP10 TP11 TP13 TP14: "Test Point, Miniature, Red, TH"
TP15 TP16 TP17 TP18: library part TP_H0.45P0.75, "Testpoint"
U1 U3 U9: "Precision, Low-Noise, Rail-to-Rail Output, 36 V, Zero-Drift Operational Amplifiers, DBV0005A"
U2 U4: "0.03 uV/degC, 6 uV Vos, Low Noise, Rail-to-Rail Output, Zero-Drift Operational Amplifier, 4 to 36 V, -40 to 105 degC, 8-pin SOIC (D0008A), Green (RoHS & no Sb/Br)"
U5: "Precision Micropower Shunt Voltage Reference, 3-pin SOT-23, Pb-Free"
U6: "Single Output High PSRR LDO, 200 mA, Fixed -2.5 V Output, -10 to -2.7 V Input, 5-pin SOT-23 (DBV), -40 to 125 degC, Green (RoHS & no Sb/Br)"
U7: "-1.8 to -5.25 V, Inverting Charge Pump Regulator, 60 mA, 1.8 to 5.25 V Input with 2-Cell Alkaline / Nixx Input, -40 to 85 degC, 5-pin SOT23 (DBV5), Green (RoHS & no Sb/Br)"
U8: "Series of Adjustable Micropower Voltage Regulators, 8-pin LLP, Pb-Free"
ZZ1: library part AssemblyNoteLabel
ZZ2 ZZ3 ZZ4: library part AssemblyNote

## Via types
v1: diameter 24, hole 12, Top Layer to Bottom Layer, tented both sides, 79 vias
v2: diameter 19.68, hole 7.87, Top Layer to Bottom Layer, 5 vias
v3: diameter 40, hole 20, Top Layer to Bottom Layer, tented both sides, 1 vias

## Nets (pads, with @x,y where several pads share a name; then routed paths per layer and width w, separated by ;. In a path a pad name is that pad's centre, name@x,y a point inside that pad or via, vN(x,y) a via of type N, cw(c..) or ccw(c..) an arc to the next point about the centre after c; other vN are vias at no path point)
+2.5V: C27.1 C28.1 D4.1 J5.1 J8.1 L2.2 R28.1 R31.2 R47.1 TP11.1 | length 2206.1
  Top Layer w20: R28.1@886.5,2075 920,2075 v1(935,2090) ; L2.2@902.56,418.5 930,418.5 952.5,396
  Top Layer w25: R47.1@945,1371.5 v1(945,1415) ; C27.1@963.78,347.32 1088.82,347.32 1141.5,400 1614.12,400 1624.49,410.37 1625.37,410.37 1679.06,464.06 J5.1@1840.55,464.06 ; 1000,393.5 TP11.1@1000,468.5 ; TP11.1@1000,483.5 TP11.1@1000,468.5 ; TP11.1@1015,483.5 TP11.1@1000,468.5 ; 1040,383.5 1070,413.5 v3(1070,468.5) ; D4.1@1205,292.97 1292.03,292.97 1294.06,295 J8.1@1415,295
  Bottom Layer w20: v1(935,2090) 975,2050 975,1575 945,1545 v1(945,1415)
+5V: C11.2 C24.1 C25.1 C30.2 D2.1 D3.2 J5.4 J6.1 J8.3 R32.1 R34.2 R36.1 R37.1 TP13.1 U3.5 U8.8 | length 6835.6
  Top Layer w20: v1(877.99,1607.01) 905,1580 1100,1580 1156.5,1636.5 v1(1156.5,1686.5) 1156.5,1746.5 1185,1775 1280,1775 1295,1760 1295,1690 1320,1665 1320,1575 1350,1545 1415,1545 1434.13,1525.87 U3.5@1434.13,1492.4 1456.1,1492.4 1470,1478.5 1470,1445 1480,1435 C11.2@1513.5,1435 v1(1513.5,1478.5)
  Top Layer w25: TP13.1@465,105 465,175 440,200 440,300 480,340 ; v1(1580,880) 1695.94,764.06 J5.4@1840.55,764.06
  Top Layer w35: J6.1@134.35,799.47 133.86,798.98 213.98,798.98 ; D3.2@315.53,850 265,850 213.98,798.98 ; C25.1@445,407.01 342.99,407.01 295,455 295,518.5 C24.1@298.5,515 315,531.5 315,585 340,610 D2.1@340,640.53 287.19,640.53 240,687.72 240,772.95 213.98,798.98
  Bottom Layer w20: R32.1@506.3,1773.23 506.3,1816.3 525,1835 820,1835 877.99,1777.01 R34.2@877.99,1680 v1(877.99,1607.01) 845,1574.02 845,1385 833.5,1373.5 R37.1@833.5,1005 ; v1(1156.5,1686.5) R36.1@1200,1686.5 C30.2@1265,1686.5
  Bottom Layer w25: TP13.1@465,105 900,105 1020,225 1285,225 J8.3@1415,95 1510,190 1510,535 1460,585 1460,760 v1(1580,880) 1635,935 1635,1145 1540,1240 1375,1240 1300,1315 1300,1420 1340,1460 1495,1460 v1(1513.5,1478.5)
-2.5V: C18.1 C21.1 D1.2 J5.3 J7.1 L1.2 R43.1 R53.1 TP10.1 | length 2999.3
  Top Layer w20: v1(440,1680) R43.1@495,1680 ; TP10.1@1190,505 1272.56,587.56 L1.2@1272.56,615 1272.56,648.56 1294.04,670.04 C21.1@1310,670.04 C21.1@1329.96,670.04
  Top Layer w25: v1(465,1005) R53.1@518.5,1005
  Top Layer w30: R53.1@518.5,1005 518.5,951.5 555,915 1475,915 1590,800 J7.1@1590,725
  Top Layer w35: C18.1@1425,738.5 1484.47,679.04 ; D1.2@1484.47,585 1484.47,679.04 ; J7.1@1590,725 1530.43,725 1484.47,679.04
  Bottom Layer w25: v1(440,1680) 295,1535 295,1235 465,1065 v1(465,1005)
  Bottom Layer w35: J7.1@1590,725 1674.06,725 1735,664.06 J5.3@1840.55,664.06
-VE_UNREG: C17.1 C19.1 TP9.1 U6.2 U6.3 U7.1 | length 466
  Top Layer w20: C17.1@640,815 642.4,812.6 U7.1@642.4,714.13 ; 949.96,799.96 996.77,799.96 U6.3@997.6,799.13
  Top Layer w30: TP9.1@740,815 795,815 810.04,799.96 C19.1@885,799.96
  Top Layer w35: C17.1@640,815 TP9.1@740,815 ; C19.1@885,799.96 949.96,799.96
GND: C1.1 C2.2 C3.1 C4.2 C5.1 C8.1 C9.2 C11.1 C12.2 C13.1 C15.2 C16.1 C17.2 C18.2 C19.2 C20.2 C21.2 C22.2 C24.2 C25.2 C26.2 C27.2 C28.2 C29.2 C30.1 C33.1 C35.1 C36.1 C37.1 C38.2 D1.1 D2.2 D4.2 D5.2 J1.2 J2.2 J3.1 J4.2 J5.2 J6.2 J7.3 R7.1 R10.1 R13.1 R16.1 R24.1 R25.1 R30.1 R38.1 R40.1 R45.1 TP8.1 U3.2 U5.2 U6.1 U7.4 U8.4 U8.9 | length 2864.8
  Top Layer w15: v1(1265,1565) 1277.4,1577.4 U5.2@1277.4,1623.66 ; U3.2@1325.87,1455 1355,1455 1370,1440 v1(1370,1415)
  Top Layer w20: v1(70,590) 70,556.5 C24.2@111.5,515 ; v1(110,590) 110,516.5 C24.2@111.5,515 ; v1(155,590) 155,558.5 C24.2@111.5,515 ; v1(335,1285) R16.1@335,1335 ; v1(420,630) C22.2@475,630 ; R10.1@426.5,1911.5 v1(426.5,1963.5) ; v1(475,580) C22.2@475,630 ; v1(485,1120) R24.1@528.5,1120 ; v1(510,815) C17.2@560,815 ; U7.4@567.6,605.87 539.13,605.87 515,630 C22.2@475,630 ; C8.1@692.99,1680 692.99,1712.99 v1(705,1725) ; C16.1@711.5,1005 v1(711.5,1045) ; v1(742.99,1961.5) C4.2@742.99,2005 ; R30.1@765,495 v1(813.5,495) ; v1(805,1420) 815,1410 C12.2@815,1371.5 ; v1(846,624) 846,647 869.04,670.04 C19.2@890,670.04 ; R13.1@877.99,1680 v1(921.5,1680) ; C13.1@880,1371.5 v1(880,1415) ; v1(886.5,1958.5) C1.1@886.5,2005 ; v1(890,624) C19.2@890,670.04 ; v1(934,624) 934,647 910.96,670.04 C19.2@890,670.04 ; C2.2@965,2035 965,2060 v1(990,2085) ; C38.2@1028.5,1375 v1(1028.5,1413.5) ; v1(1110,1445) 1130,1425 C15.2@1175,1425 ; v1(1120,156.5) C28.2@1120,207.01 ; R25.1@1125,1186.5 v1(1125,1235) ; C20.2@1180,799.96 v1(1180,845) ; v1(1205,124.5) D4.2@1205,164.04 ; v1(1209.5,1891.5) R7.1@1255,1891.5 ; v1(1214.25,1184.25) R45.1@1257.64,1184.25 ; v1(1260,108.5) 1294.53,108.5 D5.2@1295,108.98 ; C21.2@1310,799.96 v1(1310,845) ; C37.1@1402.99,1325 v1(1455,1325) ; v1(1430,1920) 1441.5,1931.5 C5.1@1480,1931.5 ; C3.1@1441.5,2055 v1(1441.5,2098.5) ; C35.1@1485,1196.5 v1(1526.5,1196.5)
  Top Layer w25: D2.2@340,769.47 v1(399.47,769.47) ; C11.1@1576.5,1435 v1(1625,1435) ; C9.2@1585,1355 v1(1650,1355) ; C36.1@1645,1196.5 1753.5,1196.5 1760,1190 J4.2@1835,1190 ; C33.1@1645,1621.5 1731.5,1621.5 1765,1655 J1.2@1834.65,1655
  Top Layer w30: v1(1355.53,530.53) D1.1@1355.53,585
  Bottom Layer w15: v1(1265,1565) C30.1@1265,1623.5
  Bottom Layer w20: v1(486.5,250) R40.1@535,250 ; v1(1066.5,561.5) R38.1@1066.5,608.7
  other v1: 795,58.5 885,58.5 965,58.5 1050,58.5 1130,58.5 730,153.5 1115,840 1425,840
  other v2: 610,366.26 570.63,413.5 610,413.5 649.37,413.5 610,460.75
NetC1_2: C1.2 R28.2 TP15.1 U2.8 | length 292.4
  Top Layer w20: TP15.1@740,2090 755,2075 R28.2@823.5,2075 C1.2@823.5,2005 823.5,1926.5 845,1905 U2.8@868.78,1905
NetC6_1: C6.1 R5.1 R10.2 U2.2 | length 231.3
  Top Layer w15: R10.2@426.5,1848.5 C6.1@496.5,1848.5 R5.1@566.5,1848.5 567.63,1847.37 603.87,1847.37 611.5,1855 U2.2@654.21,1855
NetC6_2: C6.2 R2.1 R5.2 U2.1 | length 276.6
  Top Layer w15: C6.2@496.5,1911.5 R5.2@566.5,1911.5 596.2,1911.5 602.7,1905 U2.1@654.21,1905 654.21,1930.79 611.5,1973.5 R2.1@611.5,2003.5
NetC7_1: C7.1 R3.1 R6.2 U2.7 | length 392.7
  Top Layer w15: U2.7@868.78,1855 U2.7@880,1855 ; R3.1@965,1965 965,1930 905,1870 895,1870 U2.7@880,1855 ; C7.1@1085,1848.43 1085,1845 1034.96,1845 1018.46,1861.5 R6.2@965,1861.5 943.5,1840 900,1840 885,1855 U2.7@880,1855
NetC7_2: C7.2 R6.1 R11.2 U2.6 | length 432
  Top Layer w15: U2.6@868.78,1805 910,1805 920,1795 920,1770 935,1755 950,1755 ; R11.2@965,1716.5 965,1745 955,1755 950,1755 ; C7.2@1085,1651.57 1016.5,1720.08 1016.5,1783.5 1001.5,1798.5 R6.1@965,1798.5 965,1770 950,1755
NetC8_2: C8.2 R43.2 TP16.1 U2.4 | length 244.1
  Top Layer w15: TP16.1@575,1600 557.99,1617.01 R43.2@557.99,1680 C8.2@630,1680 630,1708.5 654.21,1732.72 U2.4@654.21,1755
NetC10_1: C10.1 R18.1 R19.2 U4.1 | length 403.8
  Top Layer w15: R18.1@668.5,1310 668.5,1281.5 677.72,1272.28 U4.1@677.72,1235 645,1235 620,1260 R19.2@591.5,1260 591.5,1323.07 C10.1@708.43,1440
NetC10_2: C10.2 R19.1 R21.2 TP5.1 U4.2 | length 563.3
  Top Layer w15: TP5.1@450,1580 511.57,1518.43 C10.2@511.57,1440 511.57,1351.93 528.5,1335 R19.1@528.5,1260 528.5,1233.5 537,1225 582,1225 591.5,1215.5 R21.2@591.5,1190 596.5,1185 U4.2@677.72,1185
